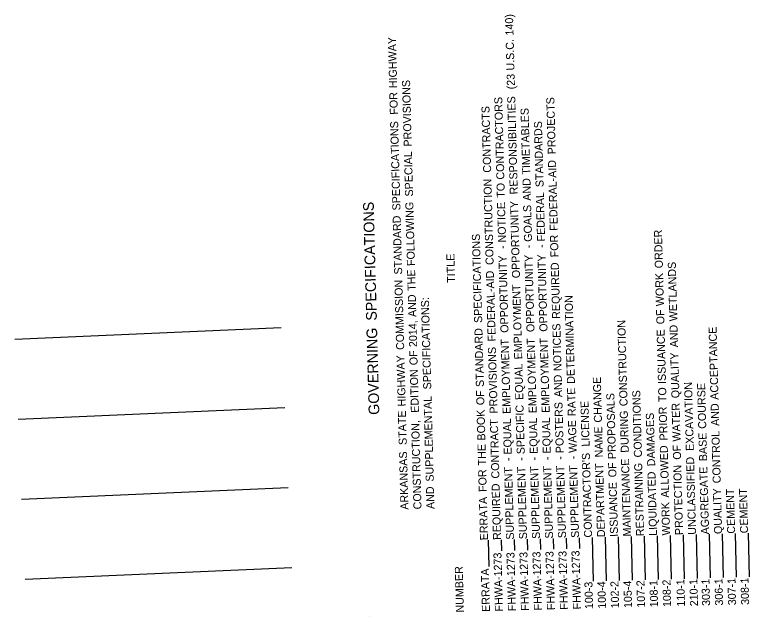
# Model space of a CAD drawing. Extents: x 1929542 to 1931706, y 595440 to 597808.
# Drawn here: x 1930579 to 1931130, y 596424 to 596875 of the extents above; entities that cross this region are included whole.
import ezdxf

# ---------------------------------------------------------------- set-up
doc = ezdxf.new("R2010")
doc.units = 0
doc.layers.add('BR_Pr_Bent_CL', color=7, linetype='Continuous')
doc.layers.add('Default', color=7, linetype='Continuous')

msp = doc.modelspace()

# ---------------------------------------------------------------- linework, layer by layer
at = {"layer": 'BR_Pr_Bent_CL'}
for p, q in [((1930779.3, 596640.34), (1930579.49, 596631.64)), ((1930781.91, 596580.39), (1930582.1, 596571.7)), ((1930784.52, 596520.45), (1930584.71, 596511.76)), ((1930787.12, 596460.51), (1930587.31, 596451.81))]:
    msp.add_line(p, q, dxfattribs=at)
at = {"layer": 'Default'}
for p, q in [((1931109.73, 596485.94), (1931110.61, 596453.19)), ((1931119.48, 596486.2), (1931120.36, 596453.45)), ((1931129.22, 596486.46), (1931130.1, 596453.72)), ((1930934.29, 596481.23), (1930934.82, 596461.63)), ((1930944.04, 596481.49), (1930944.26, 596473.37)), ((1930953.79, 596481.75), (1930954.01, 596473.63)), ((1930963.53, 596482.01), (1930963.75, 596473.9)), ((1930973.28, 596482.27), (1930973.5, 596474.16)), ((1930983.03, 596482.54), (1930983.25, 596474.42)), ((1930992.77, 596482.8), (1930992.99, 596474.68)), ((1931002.52, 596483.06), (1931002.74, 596474.94)), ((1931012.27, 596483.32), (1931013.15, 596450.58)), ((1931022.01, 596483.58), (1931022.89, 596450.84)), ((1931031.76, 596483.84), (1931032.64, 596451.1)), ((1931041.51, 596484.11), (1931042.39, 596451.36)), ((1931051.25, 596484.37), (1931052.13, 596451.62)), ((1931061, 596484.63), (1931061.88, 596451.88)), ((1931070.75, 596484.89), (1931071.62, 596452.15)), ((1931080.49, 596485.15), (1931081.37, 596452.41)), ((1931090.24, 596485.41), (1931091.12, 596452.67)), ((1931099.99, 596485.67), (1931100.86, 596452.93)), ((1930845.34, 596424.22), (1930845.34, 596424.22))]:
    msp.add_line(p, q, dxfattribs=at)

# ---------------------------------------------------------------- texts
for s, height, p in [(' 140)', 6, (1930953.46, 596857.3)), (' HIGHWAY', 6, (1930866.25, 596817.86)), (' U.S.C.', 6, (1930954.17, 596831.03)), (' (23', 6, (1930954.54, 596816.97)), (' PROVISIONS', 6, (1930877.18, 596774.08)), (' FOR', 6, (1930866.78, 596797.95)), (' CONTRACTORS', 6, (1930946.61, 596749.32)), (' RESPONSIBILITIES', 6, (1930956.66, 596738.24)), (' PROJECTS', 6, (1930985.11, 596768.28)), (' CONTRACTS', 6, (1930936.71, 596754.5)), (' TIMETABLES', 6, (1930966.01, 596753.05)), (' SPECIFICATIONS', 6, (1930868.71, 596726.21)), (' STANDARDS', 6, (1930976.02, 596743.66)), (' SPECIAL', 6, (1930878.18, 596736.65)), (' FEDERAL-AID', 6, (1930986.65, 596710.98)), (' CONSTRUCTION', 6, (1930938.57, 596685.34)), (' AND', 6, (1930966.54, 596733.47)), (' TO', 6, (1930946.97, 596735.73)), (' FEDERAL', 6, (1930977.11, 596702.97)), (' SPECIFICATIONS', 8, (1930851.04, 596642.88)), (' FOLLOWING', 6, (1930879.58, 596684.57)), (' NOTICE', 6, (1930947.87, 596702.18)), (' OPPORTUNITY', 6, (1930958.34, 596675.44)), (' GOALS', 6, (1930967.36, 596702.71)), (' STANDARD', 6, (1930870, 596678.23)), (' ORDER', 6, (1931065.43, 596682.84)), (' SPECIFICATIONS', 6, (1930929.98, 596641.88)), (' FOR', 6, (1930987.18, 596691.08)), (' -', 6, (1930948, 596697.33)), (' -', 6, (1930967.49, 596697.85)), (' -', 6, (1930977.24, 596698.11)), ('TITLE', 6, (1930909.61, 596674.19)), (' OPPORTUNITY', 6, (1930978.93, 596635.32)), (' OPPORTUNITY', 6, (1930949.69, 596634.53)), (' OPPORTUNITY', 6, (1930969.18, 596635.05)), (' WETLANDS', 6, (1931076.25, 596643.17)), (' REQUIRED', 6, (1930988.42, 596644.96)), (' THE', 6, (1930880.08, 596665.93)), (' FEDERAL-AID', 6, (1930940.11, 596628.05)), (' WORK', 6, (1931066.19, 596654.46)), (' COMMISSION', 6, (1930871.52, 596621.65)), (' EMPLOYMENT', 6, (1930959.97, 596614.6)), (' AND', 6, (1930880.61, 596646.35)), (' SPECIFICATIONS:', 6, (1930891.82, 596592.11)), (' DETERMINATION', 6, (1930999.48, 596596.29)), (' OF', 6, (1931066.56, 596640.88)), (' CONSTRUCTION', 6, (1931038.94, 596579.52)), (' 2014,', 6, (1930881.21, 596623.81)), (' NOTICES', 6, (1930989.47, 596605.82)), (' AND', 6, (1931076.78, 596623.59)), (' ACCEPTANCE', 6, (1931107.09, 596584.31)), ('GOVERNING', 8, (1930852.85, 596575.26)), (' STANDARD', 6, (1930931.27, 596593.9)), (' ISSUANCE', 6, (1931067.76, 596596.15)), (' EMPLOYMENT', 6, (1930951.32, 596573.7)), (' EMPLOYMENT', 6, (1930970.81, 596574.22)), (' EMPLOYMENT', 6, (1930980.56, 596574.48)), (' PROVISIONS', 6, (1930941.56, 596574)), (' HIGHWAY', 6, (1930872.65, 596579.34)), (' OF', 6, (1930881.58, 596610.23)), (' QUALITY', 6, (1931077.8, 596585.47)), (' EQUAL', 6, (1930960.79, 596584.16)), (' EDITION', 6, (1930882.53, 596574.6)), (' AND', 6, (1930990, 596586.25)), (' CHANGE', 6, (1931019.77, 596567.25)), (' EXCAVATION', 6, (1931088.61, 596545.97)), (' COURSE', 6, (1931097.92, 596562.56)), (' OF', 6, (1930931.63, 596580.31)), (' RATE', 6, (1931000.13, 596572.05)), (' PROPOSALS', 6, (1931030.26, 596539.83)), (' CONDITIONS', 6, (1931049.73, 596541.12)), (' TO', 6, (1931068.12, 596582.56)), (' SUPPLEMENTAL', 6, (1930893.67, 596523.01)), (' LICENSE', 6, (1931010.5, 596549.21)), (' SPECIFIC', 6, (1930961.88, 596543.52)), (' POSTERS', 6, (1930991.12, 596544.3)), (' PRIOR', 6, (1931068.9, 596553.8)), (' WATER', 6, (1931078.67, 596552.99)), (' AND', 6, (1931107.62, 596564.74)), (' STATE', 6, (1930873.43, 596550.45)), (' BOOK', 6, (1930932.35, 596553.79)), (' DURING', 6, (1931039.88, 596544.66)), (' DAMAGES', 6, (1931059.66, 596534.47)), ('           CONSTRUCTION,', 6, (1930885.07, 596479.91)), (' CONTRACT', 6, (1930942.87, 596525.28)), (' EQUAL', 6, (1930952.14, 596543.26)), (' EQUAL', 6, (1930971.63, 596543.78)), (' EQUAL', 6, (1930981.38, 596544.04)), (' WAGE', 6, (1931000.87, 596544.56)), (' NAME', 6, (1931020.47, 596541.16)), (' CONTROL', 6, (1931108.77, 596521.73)), (' BASE', 6, (1931098.57, 596538.32)), (' THE', 6, (1930932.85, 596535.14)), (' ALLOWED', 6, (1931070.05, 596510.94)), (' OF', 6, (1931079.04, 596539.41)), ('           ARKANSAS', 6, (1930875.33, 596479.64)), ("CONTRACTOR'S", 6, (1931012.27, 596483.32)), (' -', 6, (1930952.27, 596538.4)), (' -', 6, (1930962.01, 596538.66)), (' -', 6, (1930971.76, 596538.92)), (' -', 6, (1930981.51, 596539.19)), (' -', 6, (1930991.25, 596539.45)), (' -', 6, (1931001, 596539.71)), ('MAINTENANCE', 6, (1931041.51, 596484.11)), ('UNCLASSIFIED', 6, (1931090.24, 596485.41)), ('SUPPLEMENT', 6, (1930953.79, 596481.75)), ('SUPPLEMENT', 6, (1930963.53, 596482.01)), ('SUPPLEMENT', 6, (1930973.28, 596482.27)), ('SUPPLEMENT', 6, (1930983.03, 596482.54)), ('SUPPLEMENT', 6, (1930992.77, 596482.8)), ('SUPPLEMENT', 6, (1931002.52, 596483.06)), ('DEPARTMENT', 6, (1931022.01, 596483.58)), (' OF', 6, (1931030.62, 596526.24)), ('RESTRAINING', 6, (1931051.25, 596484.37)), ('PROTECTION', 6, (1931080.49, 596485.15)), ('AGGREGATE', 6, (1931099.99, 596485.67)), (' FOR', 6, (1930933.38, 596515.24)), ('LIQUIDATED', 6, (1931061, 596484.63)), ('ISSUANCE', 6, (1931031.76, 596483.84)), ('           AND', 6, (1930894.82, 596480.17)), ('REQUIRED', 6, (1930944.04, 596481.49)), ('QUALITY', 6, (1931109.73, 596485.94)), ('CEMENT', 6, (1931119.48, 596486.2)), ('CEMENT', 6, (1931129.22, 596486.46)), ('ERRATA', 6, (1930934.29, 596481.23)), ('WORK', 6, (1931070.75, 596484.89)), ('FHWA-1273', 6, (1930945.48, 596427.88)), ('FHWA-1273', 6, (1930955.23, 596428.14)), ('FHWA-1273', 6, (1930964.97, 596428.41)), ('FHWA-1273', 6, (1930974.72, 596428.67)), ('FHWA-1273', 6, (1930984.47, 596428.93)), ('FHWA-1273', 6, (1930994.21, 596429.19)), ('FHWA-1273', 6, (1931003.96, 596429.45)), ('NUMBER', 6, (1930916.24, 596427.1)), ('ERRATA', 6, (1930935.73, 596427.62)), ('308-1', 6, (1931129.99, 596432.84)), ('100-3', 6, (1931013.03, 596429.7)), ('100-4', 6, (1931022.78, 596429.96)), ('102-2', 6, (1931032.52, 596430.22)), ('105-4', 6, (1931042.27, 596430.48)), ('107-2', 6, (1931052.02, 596430.74)), ('108-1', 6, (1931061.76, 596431)), ('108-2', 6, (1931071.51, 596431.27)), ('110-1', 6, (1931081.93, 596431.55)), ('210-1', 6, (1931091.68, 596431.81)), ('303-1', 6, (1931100.75, 596432.05)), ('306-1', 6, (1931110.5, 596432.31)), ('307-1', 6, (1931120.24, 596432.57))]:
    msp.add_text(s, height=height, rotation=91.5377, dxfattribs=at).set_placement(p)

doc.saveas('drawing.dxf')
